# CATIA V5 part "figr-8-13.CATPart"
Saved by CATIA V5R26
Part number: Part1
Bounding box of the stored display mesh (mm): x 4.549 to 89.781, y -52.238 to 26.36, z 54 to 147.773
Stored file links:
  D:\_Deepak\CATIA\CATIA V5-6R2016_Deepak\Resources\Part files\Partfiles\c08_catia_v5_6r2016_prt\figr-8-13.CATPart
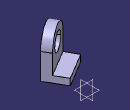
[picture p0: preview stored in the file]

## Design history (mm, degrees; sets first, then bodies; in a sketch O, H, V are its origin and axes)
Body1 (main body)
  Sketch1 on yz-plane, origin (0, 0, 0), H (0, 1, 0), V (0, 0, 1)
    point P1 (-104.4861, 0)
    line L1 (-104.4861, 0) -> (-104.4861, 44.267)
    arc A1 centre (-69.7903, 44.267) radius 34.6958 from (-104.4861, 44.267) to (-35.0946, 44.267) cw
    line L2 (-35.0946, 44.267) -> (-35.0946, 0)
    point P5 (-35.0946, 0)
    line L3 (-35.0946, 0) -> (-104.4861, 0)
    circle A2 centre (-69.7903, 44.267) radius 19.5413
    coincidence: P1 H, P5 H
    vertical: L1 V
    tangency: A1 L1, L2 A1
    horizontal: L3 H
  Pad1: profile Sketch1, direction (1, 0, 0), length 20
  Sketch2 on face of Pad1, origin (0, 0, 0), H (0, -1, 0), V (0, 0, 1)
    point P1 (35.0946, 0)
    line L1 (35.0946, 0) -> (104.4861, 0)
    line L2 (104.4861, 0) -> (104.4861, -15)
    line L3 (104.4861, -15) -> (35.0946, -15)
    line L4 (35.0946, -15) -> (35.0946, 0)
    reference projected line E1 (35.0946, 0) -> (35.0946, 44.267) from edge [face of Pad1 | face of Pad1]
    reference projected line E2 (104.4861, 44.267) -> (104.4861, 0) from edge [face of Pad1 | face of Pad1]
    distance L3 L1 = 15
    coincidence: P1 H, L4 E1, L2 E2
    horizontal: L1 H, L3 H
    vertical: L2 V, L4 V
  Pad2: profile Sketch2, direction (1, 0, 0), length 50
  Translate1: ToTransfor Pad2, Direction xy-plane, Length 69
  Rotate1: ToTransfor Translate1, Axis edge, Angle 121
